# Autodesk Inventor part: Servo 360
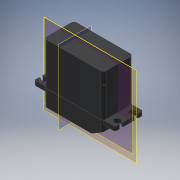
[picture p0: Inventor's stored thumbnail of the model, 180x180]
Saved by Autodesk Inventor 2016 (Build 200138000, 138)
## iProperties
Created: 2015-06
Part Number: Servo 360
Material: Generic
Document SubType Name: Modeling
Designer: Luis
Density: 1 g/cm^3
Appearance: Rubber - Black - Version 1.1
Author: Luis
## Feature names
1. Extrusion1
2. Chamfer1
3. Fillet2
4. Extrusion3
5. Fillet3
6. Fillet4
7. Mirror1
8. Sweep1
9. Extrusion4
10. Extrusion5
11. Extrusion6
12. Fillet5
13. Fillet6
14. Fillet7
15. Fillet8
16. Fillet9
17. Fillet10
18. Fillet11
19. Extrusion7
20. Extrusion8
21. Circular Pattern1
22. Extrusion9
23. Fillet12
## Parameters: d0 = 40.005 mm, d2 = 39.5 mm, d3 = 20.2184 mm, d4 = 0, d5 = 8 mm, d6 = 2 mm, d7 = 30 deg, d26 = -11 mm, d27 = 0.65 mm, d28 = 0.65 mm, d30 = 2 mm, d31 = 7.3 mm, d32 = 18.75 mm, d34 = 2.8 mm, d35 = 4 mm, d38 = 2.7 mm, d39 = 0, d40 = 1 mm, d41 = 0.5 mm, d42 = -8 mm, d43 = 0.65 mm, d44 = 0.65 mm, d45 = 0.65 mm, d46 = 0.65 mm, d47 = 0, d49 = 13 mm, d50 = 7 mm, d51 = 2.45 mm, d52 = 0, d53 = 6 mm, d54 = 0, d56 = 4 mm, d57 = 4 mm, d58 = 2.5 mm, d59 = 2 mm, d60 = 0, d61 = 0.5 mm, d62 = 0.5 mm, d63 = 0.5 mm, d64 = 0.5 mm, d65 = 0.5 mm, d66 = 0.5 mm, d67 = 0.5 mm, d68 = 0.3 mm, d69 = 0, d70 = 0.5 mm, d71 = 0.5 mm, d72 = 5 mm, d73 = 0, d75 = 360 deg, d77 = 1.5 mm, d78 = 5 mm, d79 = 0, d80 = 0.5 mm, d81 = 0
